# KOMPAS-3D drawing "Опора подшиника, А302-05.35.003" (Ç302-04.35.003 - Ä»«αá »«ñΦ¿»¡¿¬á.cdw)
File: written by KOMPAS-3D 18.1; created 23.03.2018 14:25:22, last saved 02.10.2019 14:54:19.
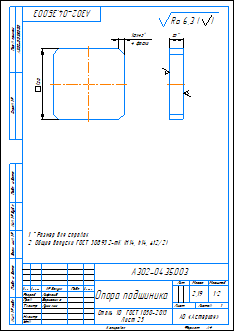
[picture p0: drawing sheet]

Sheet 1: A4, portrait

Document properties: Полное имя файла: D:\Мембранные насосы\Мембранный электропривод\А302-00.00.000 - ASTRA-302 (МЭ200)\А302-04.00.000 - Мембранный насос ASTRA-302-PP Чертежи\А302-04.35.003 - Опора подшипника.cdw; Автор: Милов; Масса: 2.19132; Параметр неуказанной шероховатости: Ra 6,3

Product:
- Part/product: Опора подшиника  | designation А302-05.35.003
    Масса: 10.2382
- Part/product: Опора подшиника  | designation А302-04.35.003
    Масса: 2.19132

Title block, sheet 1: Наименование: Опора подшиника; designation: А302-04.35.003; Материал: Сталь 10  ГОСТ 1050-2013 / Лист 25; Масса: 2,19; scale: 1:2; Количество листов документа: 1; organisation: АО «Астерион»; Форматы листов документа: A4; stored path: \\192.168.87.28\Konstructor_doc\Мембранные насосы\Мембранный электропривод\А302-00.00.000 - ASTRA-302 (МЭ200)\Чертежи\А302-00.35.002 - Пластина.cdw; Разработал: Лифлянд; Проверил: Борисенко; Т. контр.: Лучихин

Views: Вид 1, Проекционный вид 2
Referenced files in D:\Мембранные насосы\Мембранный электропривод\А302-00.00.000 - ASTRA-302 (МЭ200)\3Д ПВХ\: А302-04.35.003 - Опора подшиника.m3d
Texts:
  Ra 6,3
  Ra 6,3 ( )
Dimensions and other numbers on the sheet: 128; 10; 4 фаски; 25; 1:2; 1; 2,19

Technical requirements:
  *Размер для справок.
  Общие допуски ГОСТ 30893.2-mK (H14, h14,  t2/2).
